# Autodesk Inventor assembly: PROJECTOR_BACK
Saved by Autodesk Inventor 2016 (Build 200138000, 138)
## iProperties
Created: 2015-11
Part Number: PROJECTOR_BACK
Document SubType Name: Assembly
Designer: John
Author: John
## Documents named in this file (8)
- D:\3D Printer Designs\John Ledden Designs\DLP Printer\V0-4\PROJECTOR_BACK.iam
- D:\3D Printer Designs\John Ledden Designs\DLP Printer\V0-4\BasePlate.ipt
- D:\3D Printer Designs\John Ledden Designs\DLP Printer\V0-4\Frame_Back.ipt
- D:\3D Printer Designs\John Ledden Designs\DLP Printer\V0-4\Frame_ProjectorBase.ipt
- D:\3D Printer Designs\John Ledden Designs\DLP Printer\V0-4\Projector_Vertical.iam
- D:\3D Printer Designs\John Ledden Designs\DLP Printer\V0-4\Projector_Horizontal.iam
- D:\3D Printer Designs\John Ledden Designs\DLP Printer\V0-4\M5_Nut.ipt
- D:\3D Printer Designs\John Ledden Designs\DLP Printer\V0-4\M5_30.ipt
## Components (19 placed, 19 different names)
1. BasePlate_1012
2. Frame_Back_1013
3. Frame_ProjectorBase_1014
4. Projector_Vertical_1015 [sub-assembly]
5. Projector_Horizontal_1016 [sub-assembly]
6. M5_Nut_1017
7. M5_30_1018
8. M5_30_1019
9. M5_Nut_1020
10. M5_Nut_1021
11. M5_30_1022
12. M5_Nut_1023
13. M5_Nut_1024
14. M5_30_1025
15. M5_30_1026
16. M5_30_1027
17. M5_30_1028
18. M5_Nut_1029
19. M5_Nut_1030
